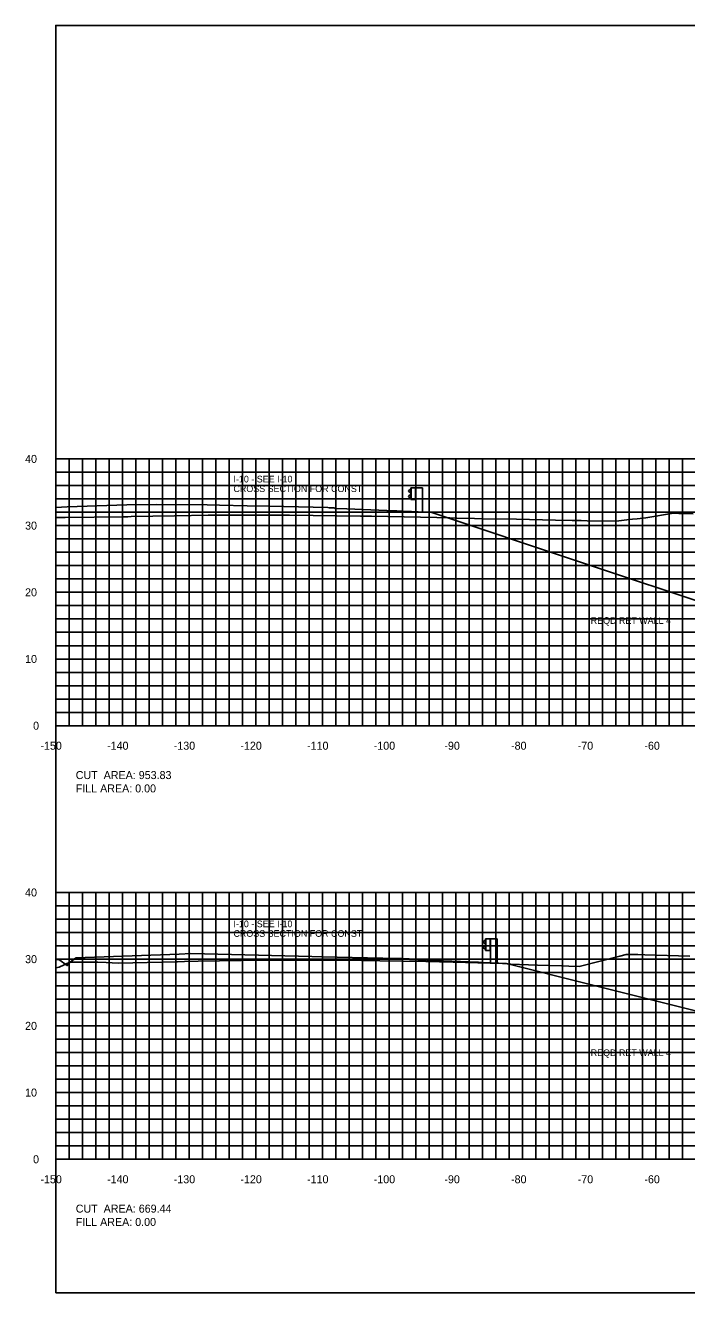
# Model space of a CAD drawing. Extents: x 1800976 to 1805104, y 250057 to 250580.
# Drawn here: x 1803496.4 to 1803595.6, y 250079.4 to 250269.4 of the extents above; entities that cross this region are included whole.
import ezdxf

# ---------------------------------------------------------------- set-up
doc = ezdxf.new("R2010")
doc.units = 0
for name, color, linetype in [('10', 7, 'Continuous'), ('3', 7, 'Continuous'), ('31', 7, 'Continuous'), ('60', 7, 'Continuous'), ('ANNO-TXT', 7, 'Continuous'), ('CL-CNST', 7, 'Continuous'), ('Level 1', 7, 'Continuous'), ('Level 62', 7, 'Continuous'), ('M-ROADS', 7, 'Continuous')]:
    doc.layers.add(name, color=color, linetype=linetype)

msp = doc.modelspace()

# ---------------------------------------------------------------- linework, layer by layer
msp.add_lwpolyline([(1803501, 250079.43), (1803801, 250079.43), (1803801, 250269.43), (1803501, 250269.43)], close=True)
at = {"layer": '60'}
for p, q in [((1803500.94, 250204.43), (1803501, 250204.43)), ((1803501, 250164.43), (1803501, 250204.43)), ((1803500.94, 250194.43), (1803501, 250194.43)), ((1803500.94, 250184.43), (1803501, 250184.43)), ((1803500.94, 250174.43), (1803501, 250174.43)), ((1803500.94, 250164.43), (1803501, 250164.43)), ((1803501, 250164.43), (1803801, 250164.43)), ((1803501, 250164.37), (1803501, 250164.43)), ((1803511, 250164.37), (1803511, 250164.43)), ((1803521, 250164.37), (1803521, 250164.43)), ((1803531, 250164.37), (1803531, 250164.43)), ((1803541, 250164.37), (1803541, 250164.43)), ((1803551, 250164.37), (1803551, 250164.43)), ((1803561, 250164.37), (1803561, 250164.43)), ((1803571, 250164.37), (1803571, 250164.43)), ((1803581, 250164.37), (1803581, 250164.43)), ((1803591, 250164.37), (1803591, 250164.43)), ((1803500.94, 250139.43), (1803501, 250139.43)), ((1803501, 250099.43), (1803501, 250139.43)), ((1803500.94, 250129.43), (1803501, 250129.43)), ((1803500.94, 250119.43), (1803501, 250119.43)), ((1803500.94, 250109.43), (1803501, 250109.43)), ((1803500.94, 250099.43), (1803501, 250099.43)), ((1803501, 250099.43), (1803801, 250099.43)), ((1803501, 250099.37), (1803501, 250099.43)), ((1803511, 250099.37), (1803511, 250099.43)), ((1803521, 250099.37), (1803521, 250099.43)), ((1803531, 250099.37), (1803531, 250099.43)), ((1803541, 250099.37), (1803541, 250099.43)), ((1803551, 250099.37), (1803551, 250099.43)), ((1803561, 250099.37), (1803561, 250099.43)), ((1803571, 250099.37), (1803571, 250099.43)), ((1803581, 250099.37), (1803581, 250099.43)), ((1803591, 250099.37), (1803591, 250099.43))]:
    msp.add_line(p, q, dxfattribs=at)
at = {"layer": 'CL-CNST'}
msp.add_line((1803568.59, 250128.86), (1803568.59, 250128.86), dxfattribs=at)
for points in [[(1803501, 250197.17), (1803502.73, 250197.24), (1803511.65, 250197.57), (1803516.1, 250197.58), (1803523.71, 250197.56), (1803525.55, 250197.52), (1803529.73, 250197.42), (1803532.99, 250197.34), (1803541.8, 250197.13), (1803542.02, 250197.12), (1803542.8, 250197.09), (1803542.82, 250197.07), (1803542.88, 250197.02), (1803544.69, 250196.94), (1803551.86, 250196.64), (1803552.18, 250196.63), (1803553.87, 250196.56), (1803554.38, 250196.53), (1803557.4, 250196.41), (1803579.4, 250189.07), (1803600.75, 250181.95), (1803601.46, 250181.95), (1803605.24, 250181.95)], [(1803501, 250129.4), (1803501.26, 250129.39), (1803501.48, 250129.38), (1803502.7, 250128.48), (1803502.74, 250128.46), (1803502.74, 250128.46), (1803502.74, 250128.7), (1803503.96, 250129.58), (1803504, 250129.61), (1803519.52, 250130.2), (1803521.28, 250130.27), (1803531.42, 250130.03), (1803533.34, 250129.98), (1803539.39, 250129.84), (1803540.92, 250129.8), (1803550.05, 250129.58), (1803553, 250129.51), (1803553.74, 250129.48), (1803554, 250129.47), (1803554.05, 250129.42), (1803554.07, 250129.4), (1803560.44, 250129.13), (1803563.06, 250129.02), (1803564.44, 250128.96), (1803565.07, 250128.94), (1803567.46, 250128.84), (1803568.6, 250128.79), (1803580.55, 250125.79), (1803600.75, 250120.73)]]:
    msp.add_lwpolyline(points, dxfattribs=at)
at = {"layer": 'Level 1'}
for p, q in [((1803554.29, 250199.95), (1803553.93, 250199.65)), ((1803554.29, 250200.1), (1803554.29, 250198.35)), ((1803556.04, 250200.1), (1803554.29, 250200.1)), ((1803554.34, 250200.1), (1803554.34, 250198.35)), ((1803554.99, 250200.1), (1803554.99, 250198.35)), ((1803555.04, 250200.1), (1803555.04, 250196.57)), ((1803556.04, 250200.1), (1803556.04, 250196.53)), ((1803553.93, 250199.58), (1803554.29, 250199.29)), ((1803554.29, 250199.15), (1803553.93, 250198.85)), ((1803553.93, 250198.78), (1803554.29, 250198.5)), ((1803555.04, 250198.35), (1803554.29, 250198.35)), ((1803565.49, 250132.33), (1803565.13, 250132.03)), ((1803565.13, 250131.96), (1803565.49, 250131.68)), ((1803565.49, 250131.54), (1803565.13, 250131.24)), ((1803565.49, 250132.48), (1803565.49, 250130.73)), ((1803567.24, 250132.48), (1803565.49, 250132.48)), ((1803565.54, 250132.48), (1803565.54, 250130.73)), ((1803566.19, 250132.48), (1803566.19, 250130.73)), ((1803566.24, 250132.48), (1803566.24, 250128.96)), ((1803567.24, 250132.48), (1803567.24, 250128.92)), ((1803565.13, 250131.17), (1803565.49, 250130.88)), ((1803566.24, 250130.73), (1803565.49, 250130.73))]:
    msp.add_line(p, q, dxfattribs=at)
for centre in [(1803553.96, 250199.62), (1803553.96, 250198.82), (1803565.16, 250132), (1803565.16, 250131.2)]:
    msp.add_arc(centre, 0.05, 135, 226.6208, dxfattribs=at)
at = {"layer": 'Level 62'}
for p, q in [((1803501, 250204.43), (1803801, 250204.43)), ((1803501, 250164.43), (1803501, 250204.43)), ((1803503, 250164.43), (1803503, 250204.43)), ((1803505, 250164.43), (1803505, 250204.43)), ((1803507, 250164.43), (1803507, 250204.43)), ((1803509, 250164.43), (1803509, 250204.43)), ((1803511, 250164.43), (1803511, 250204.43)), ((1803513, 250164.43), (1803513, 250204.43)), ((1803515, 250164.43), (1803515, 250204.43)), ((1803517, 250164.43), (1803517, 250204.43)), ((1803519, 250164.43), (1803519, 250204.43)), ((1803521, 250164.43), (1803521, 250204.43)), ((1803523, 250164.43), (1803523, 250204.43)), ((1803525, 250164.43), (1803525, 250204.43)), ((1803527, 250164.43), (1803527, 250204.43)), ((1803529, 250164.43), (1803529, 250204.43)), ((1803531, 250164.43), (1803531, 250204.43)), ((1803533, 250164.43), (1803533, 250204.43)), ((1803535, 250164.43), (1803535, 250204.43)), ((1803537, 250164.43), (1803537, 250204.43)), ((1803539, 250164.43), (1803539, 250204.43)), ((1803541, 250164.43), (1803541, 250204.43)), ((1803543, 250164.43), (1803543, 250204.43)), ((1803545, 250164.43), (1803545, 250204.43)), ((1803547, 250164.43), (1803547, 250204.43)), ((1803549, 250164.43), (1803549, 250204.43)), ((1803551, 250164.43), (1803551, 250204.43)), ((1803553, 250164.43), (1803553, 250204.43)), ((1803555, 250164.43), (1803555, 250204.43)), ((1803557, 250164.43), (1803557, 250204.43)), ((1803559, 250164.43), (1803559, 250204.43)), ((1803561, 250164.43), (1803561, 250204.43)), ((1803563, 250164.43), (1803563, 250204.43)), ((1803565, 250164.43), (1803565, 250204.43)), ((1803567, 250164.43), (1803567, 250204.43)), ((1803569, 250164.43), (1803569, 250204.43)), ((1803571, 250164.43), (1803571, 250204.43)), ((1803573, 250164.43), (1803573, 250204.43)), ((1803575, 250164.43), (1803575, 250204.43)), ((1803577, 250164.43), (1803577, 250204.43)), ((1803579, 250164.43), (1803579, 250204.43)), ((1803581, 250164.43), (1803581, 250204.43)), ((1803583, 250164.43), (1803583, 250204.43)), ((1803585, 250164.43), (1803585, 250204.43)), ((1803587, 250164.43), (1803587, 250204.43)), ((1803589, 250164.43), (1803589, 250204.43)), ((1803591, 250164.43), (1803591, 250204.43)), ((1803593, 250164.43), (1803593, 250204.43)), ((1803595, 250164.43), (1803595, 250204.43)), ((1803501, 250202.43), (1803801, 250202.43)), ((1803501, 250200.43), (1803801, 250200.43)), ((1803501, 250198.43), (1803801, 250198.43)), ((1803501, 250196.43), (1803801, 250196.43)), ((1803501, 250194.43), (1803801, 250194.43)), ((1803501, 250192.43), (1803801, 250192.43)), ((1803501, 250190.43), (1803801, 250190.43)), ((1803501, 250188.43), (1803801, 250188.43)), ((1803501, 250186.43), (1803801, 250186.43)), ((1803501, 250184.43), (1803801, 250184.43)), ((1803501, 250182.43), (1803801, 250182.43)), ((1803501, 250180.43), (1803801, 250180.43)), ((1803501, 250178.43), (1803801, 250178.43)), ((1803501, 250176.43), (1803801, 250176.43)), ((1803501, 250174.43), (1803801, 250174.43)), ((1803501, 250172.43), (1803801, 250172.43)), ((1803501, 250170.43), (1803801, 250170.43)), ((1803501, 250168.43), (1803801, 250168.43)), ((1803501, 250166.43), (1803801, 250166.43)), ((1803501, 250164.43), (1803801, 250164.43)), ((1803501, 250139.43), (1803801, 250139.43)), ((1803501, 250099.43), (1803501, 250139.43)), ((1803503, 250099.43), (1803503, 250139.43)), ((1803505, 250099.43), (1803505, 250139.43)), ((1803507, 250099.43), (1803507, 250139.43)), ((1803509, 250099.43), (1803509, 250139.43)), ((1803511, 250099.43), (1803511, 250139.43)), ((1803513, 250099.43), (1803513, 250139.43)), ((1803515, 250099.43), (1803515, 250139.43)), ((1803517, 250099.43), (1803517, 250139.43)), ((1803519, 250099.43), (1803519, 250139.43)), ((1803521, 250099.43), (1803521, 250139.43)), ((1803523, 250099.43), (1803523, 250139.43)), ((1803525, 250099.43), (1803525, 250139.43)), ((1803527, 250099.43), (1803527, 250139.43)), ((1803529, 250099.43), (1803529, 250139.43)), ((1803531, 250099.43), (1803531, 250139.43)), ((1803533, 250099.43), (1803533, 250139.43)), ((1803535, 250099.43), (1803535, 250139.43)), ((1803537, 250099.43), (1803537, 250139.43)), ((1803539, 250099.43), (1803539, 250139.43)), ((1803541, 250099.43), (1803541, 250139.43)), ((1803543, 250099.43), (1803543, 250139.43)), ((1803545, 250099.43), (1803545, 250139.43)), ((1803547, 250099.43), (1803547, 250139.43)), ((1803549, 250099.43), (1803549, 250139.43)), ((1803551, 250099.43), (1803551, 250139.43)), ((1803553, 250099.43), (1803553, 250139.43)), ((1803555, 250099.43), (1803555, 250139.43)), ((1803557, 250099.43), (1803557, 250139.43)), ((1803559, 250099.43), (1803559, 250139.43)), ((1803561, 250099.43), (1803561, 250139.43)), ((1803563, 250099.43), (1803563, 250139.43)), ((1803565, 250099.43), (1803565, 250139.43)), ((1803567, 250099.43), (1803567, 250139.43)), ((1803569, 250099.43), (1803569, 250139.43)), ((1803571, 250099.43), (1803571, 250139.43)), ((1803573, 250099.43), (1803573, 250139.43)), ((1803575, 250099.43), (1803575, 250139.43)), ((1803577, 250099.43), (1803577, 250139.43)), ((1803579, 250099.43), (1803579, 250139.43)), ((1803581, 250099.43), (1803581, 250139.43)), ((1803583, 250099.43), (1803583, 250139.43)), ((1803585, 250099.43), (1803585, 250139.43)), ((1803587, 250099.43), (1803587, 250139.43)), ((1803589, 250099.43), (1803589, 250139.43)), ((1803591, 250099.43), (1803591, 250139.43)), ((1803593, 250099.43), (1803593, 250139.43)), ((1803595, 250099.43), (1803595, 250139.43)), ((1803501, 250137.43), (1803801, 250137.43)), ((1803501, 250135.43), (1803801, 250135.43)), ((1803501, 250133.43), (1803801, 250133.43)), ((1803501, 250131.43), (1803801, 250131.43)), ((1803501, 250129.43), (1803801, 250129.43)), ((1803501, 250127.43), (1803801, 250127.43)), ((1803501, 250125.43), (1803801, 250125.43)), ((1803501, 250123.43), (1803801, 250123.43)), ((1803501, 250121.43), (1803801, 250121.43)), ((1803501, 250119.43), (1803801, 250119.43)), ((1803501, 250117.43), (1803801, 250117.43)), ((1803501, 250115.43), (1803801, 250115.43)), ((1803501, 250113.43), (1803801, 250113.43)), ((1803501, 250111.43), (1803801, 250111.43)), ((1803501, 250109.43), (1803801, 250109.43)), ((1803501, 250107.43), (1803801, 250107.43)), ((1803501, 250105.43), (1803801, 250105.43)), ((1803501, 250103.43), (1803801, 250103.43)), ((1803501, 250101.43), (1803801, 250101.43)), ((1803501, 250099.43), (1803801, 250099.43))]:
    msp.add_line(p, q, dxfattribs=at)
at = {"layer": 'M-ROADS'}
for points in [[(1803501, 250195.64), (1803502.32, 250195.66), (1803502.34, 250195.66), (1803502.41, 250195.66), (1803511.05, 250195.75), (1803511.81, 250195.77), (1803512.3, 250195.78), (1803518.83, 250195.92), (1803523.87, 250196.02), (1803531.22, 250196.01), (1803536.07, 250196), (1803546.74, 250195.85), (1803548.35, 250195.83), (1803558.15, 250195.65), (1803559.9, 250195.62), (1803560.11, 250195.61), (1803561.15, 250195.57), (1803563.82, 250195.5), (1803565.13, 250195.47), (1803570.13, 250195.38), (1803575.95, 250195.26), (1803578.45, 250195.22), (1803579.83, 250195.19), (1803580.72, 250195.17), (1803585.06, 250195.1), (1803587.07, 250195.34), (1803587.51, 250195.38), (1803588.23, 250195.47), (1803589.54, 250195.61), (1803593.65, 250196.29), (1803594.48, 250196.26), (1803595.07, 250196.24), (1803596.6, 250196.21)], [(1803501, 250128.13), (1803501.49, 250128.25), (1803503.12, 250128.96), (1803505.17, 250128.96), (1803505.37, 250128.96), (1803507.3, 250128.96), (1803508.55, 250128.91), (1803510.36, 250128.82), (1803516.89, 250128.98), (1803519.08, 250129.04), (1803519.27, 250129.04), (1803520.32, 250129.08), (1803522.37, 250129.12), (1803532.02, 250129.28), (1803537.1, 250129.27), (1803544.13, 250129.28), (1803549.6, 250129.2), (1803556.54, 250129.09), (1803560.61, 250128.99), (1803568.03, 250128.79), (1803568.15, 250128.79), (1803569.28, 250128.7), (1803570.56, 250128.65), (1803573.26, 250128.53), (1803576.89, 250128.43), (1803577.97, 250128.4), (1803579.53, 250128.35), (1803585.63, 250129.88), (1803586.59, 250130.12), (1803587.44, 250130.11), (1803588.32, 250130.11), (1803589.37, 250130.1), (1803596.13, 250129.87)]]:
    msp.add_lwpolyline(points, dxfattribs=at)

# ---------------------------------------------------------------- texts
at = {"layer": '10'}
for s, p in [('-150', (1803498.7, 250160.83)), ('-140', (1803508.7, 250160.83)), ('-130', (1803518.7, 250160.83)), ('-120', (1803528.7, 250160.83)), ('-110', (1803538.7, 250160.83)), ('-100', (1803548.7, 250160.83)), ('-90', (1803559.3, 250160.83)), ('-80', (1803569.3, 250160.83)), ('-70', (1803579.3, 250160.83)), ('-60', (1803589.3, 250160.83)), ('-150', (1803498.7, 250095.83)), ('-140', (1803508.7, 250095.83)), ('-130', (1803518.7, 250095.83)), ('-120', (1803528.7, 250095.83)), ('-110', (1803538.7, 250095.83)), ('-100', (1803548.7, 250095.83)), ('-90', (1803559.3, 250095.83)), ('-80', (1803569.3, 250095.83)), ('-70', (1803579.3, 250095.83)), ('-60', (1803589.3, 250095.83))]:
    msp.add_text(s, height=1.2, dxfattribs=at).set_placement(p)
at = {"layer": '3'}
for s, p in [('I-10 - SEE I-10 ', (1803527.66, 250200.9)), ('CROSS SECTION FOR CONST ', (1803527.66, 250199.46)), ('REQD RET WALL 4', (1803581.25, 250179.7)), ('I-10 - SEE I-10 ', (1803527.66, 250134.22)), ('CROSS SECTION FOR CONST ', (1803527.66, 250132.78)), ('REQD RET WALL 4', (1803581.25, 250114.9))]:
    msp.add_text(s, height=1, dxfattribs=at).set_placement(p)
at = {"layer": '31'}
for s, p in [('40', (1803496.4, 250203.83)), ('30', (1803496.4, 250193.83)), ('20', (1803496.4, 250183.83)), ('10', (1803496.4, 250173.83)), ('0', (1803497.6, 250163.83)), ('40', (1803496.4, 250138.83)), ('30', (1803496.4, 250128.83)), ('20', (1803496.4, 250118.83)), ('10', (1803496.4, 250108.83)), ('0', (1803497.6, 250098.83))]:
    msp.add_text(s, height=1.2, dxfattribs=at).set_placement(p)
at = {"layer": '60'}
for p in [(1803501, 250164.43), (1803501, 250099.43)]:
    msp.add_text('-', height=0.0001, dxfattribs=at).set_placement(p)
at = {"layer": 'ANNO-TXT'}
for s, p in [('CUT  AREA: 953.83', (1803504, 250156.43)), ('FILL AREA: 0.00', (1803504, 250154.43)), ('CUT  AREA: 669.44', (1803504, 250091.43)), ('FILL AREA: 0.00', (1803504, 250089.43))]:
    msp.add_text(s, height=1.2, dxfattribs=at).set_placement(p)

doc.saveas('drawing.dxf')
